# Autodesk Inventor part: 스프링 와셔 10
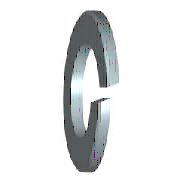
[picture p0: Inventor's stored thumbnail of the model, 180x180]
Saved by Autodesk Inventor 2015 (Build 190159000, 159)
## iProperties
Created: 2012-02
Part Number: 스프링 와셔 10
Material: 강철, 연강
Description: 스프링 잠금 와셔
Document SubType Name: Modeling
Standard: KS B 1324
Designer: mduedu
Standards Organization: KS
Language: ko-KR
Size Designation: 번호 2 - 10
Categories: <MemberInstance><Categories><Category DisplayName="조임쇠" InternalName="e4da775c-781d-43d5-af7c-5136215cf5a6" Mnemonic="FSTN"><Category DisplayName="와셔" InternalN
Density: 1 g/cm^3
Appearance: 강철
IsCustomPart: 1
Author: mduedu
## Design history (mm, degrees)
sketch "스케치1"
  geometry: C1 r 8.8 at (0, 0); C2 r 5.1 at (0, 0); 1 further point
  constraints: 2 centre point, 2 coincident
  dimensions: "d0" = 10.2 diameter of C2 (= SD1); "d1" = 17.6 diameter of C1 (= SD2)
extrude "본체" new body sketch "스케치1" distance "d2" = 2.5 (= SD); taper "d3" = 0 deg
sketch "스케치2"
  geometry: L1 (0, -5.1)-(0, 5.1) reference; L2 (2.5, 8.8)-(2.5, -8.8) reference; L3 (-1.2, 0)-(7.2, 0) reference; L4 (0, -0.5)-(2.5, 0.41); L5 (0, 0.5)-(2.5, 1.41)
  constraints: 4 end point, 4 point on line, 1 parallel
  dimensions: "d4" = 0.5 distance from line of L3 L4.start (= 0.2 x SD); "d5" = 0.5 distance from line of L3 L5.start (= 0.2 x SD); "d6" = 70 deg angle of L2 L4 (= FAWI)
extrude "절단부" cut sketch "스케치2" stored distance "d7" = 2.5 (= SD); taper "d8" = 0 deg
workaxis "Work Axis1"
workplane "Work Plane1"
body "Solid1"
other parameters: "SD1" = 10.2 [user parameter; used in 1 equation term], "SD2" = 17.6 [user parameter; used in 1 equation term], "SD" = 2.5 [user parameter; used in 4 equation terms], "FAWI" = 70 deg [user parameter; used in 1 equation term], "d9" = 0, "d10" = 0, "d11" = 0, "d12" = 0, "SDI" = 3.7 [user parameter]
